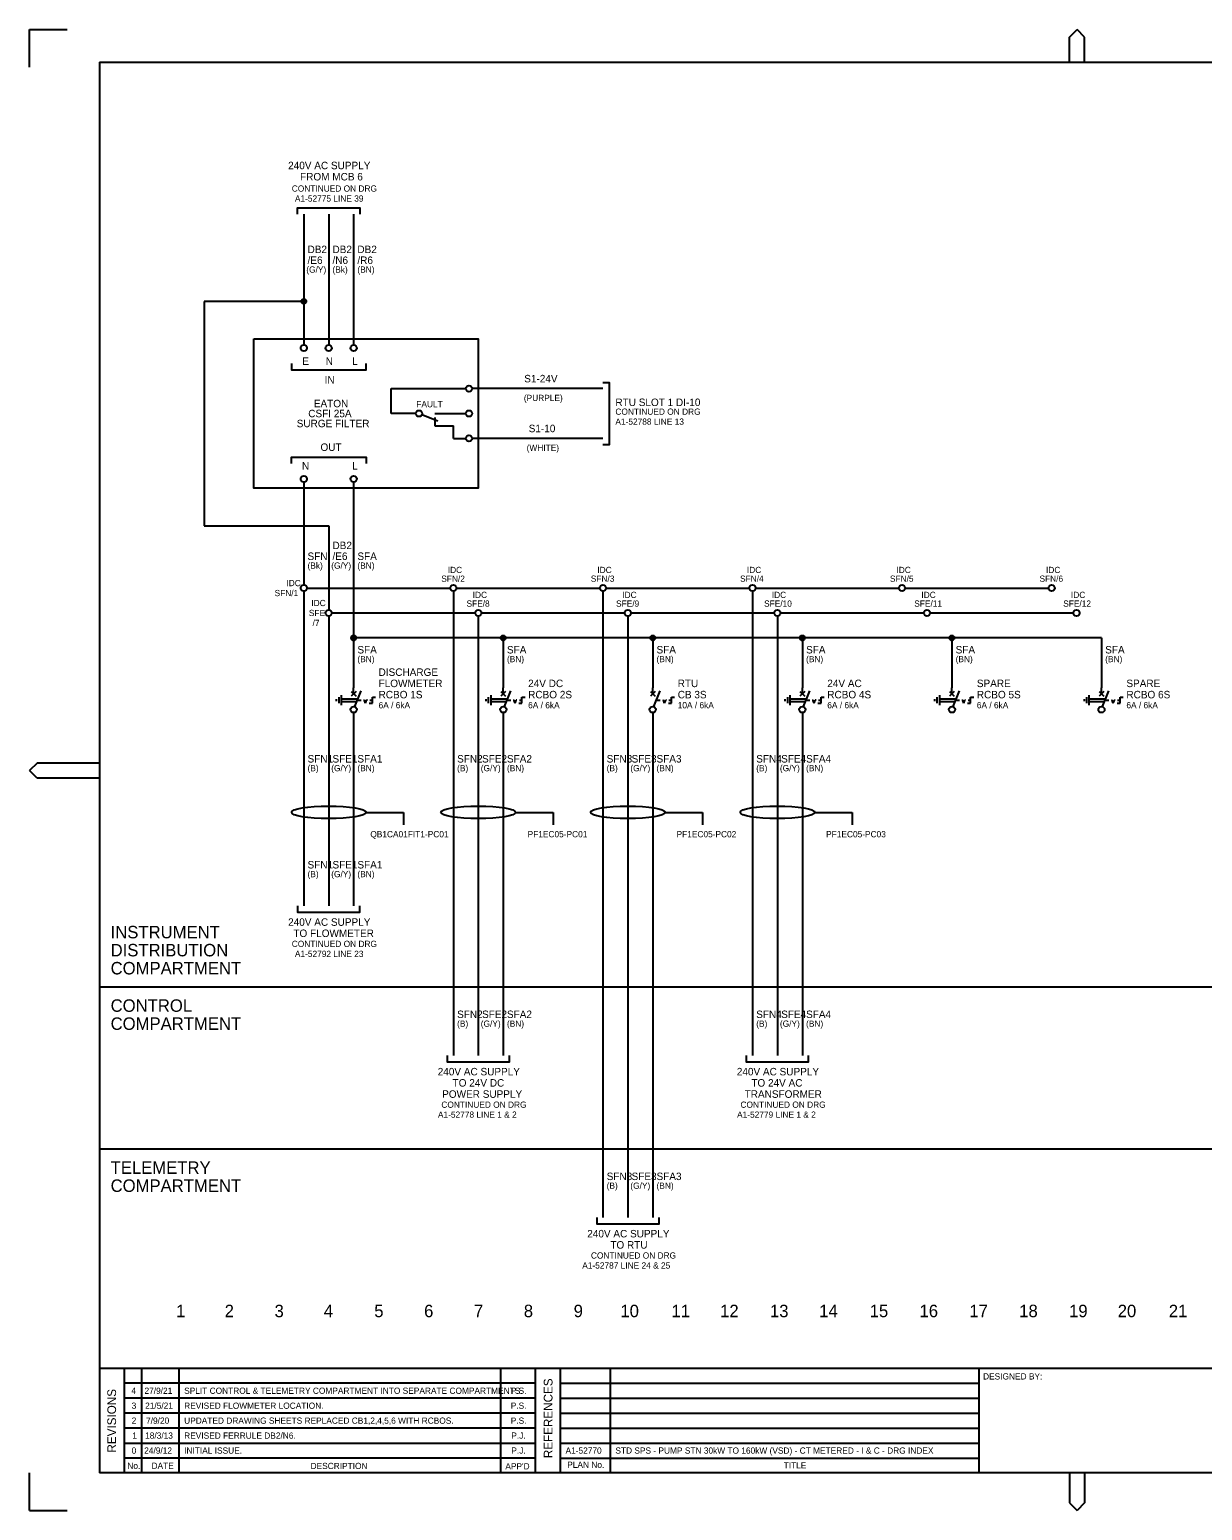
# Model space of a CAD drawing. Extents: x 0 to 841, y 0 to 594.
# Drawn here: x 0 to 470, y 0 to 594 of the extents above; entities that cross this region are included whole.
import ezdxf

# ---------------------------------------------------------------- set-up
doc = ezdxf.new("R2010")
doc.units = 0
for name, color, linetype in [('A1BORDER', 7, 'Continuous'), ('Level 1', 7, 'Continuous'), ('Level 10', 7, 'Continuous')]:
    doc.layers.add(name, color=color, linetype=linetype)

msp = doc.modelspace()

# ---------------------------------------------------------------- linework, layer by layer
at = {"layer": 'A1BORDER'}
for p, q in [((0, 594), (15, 594)), ((0, 579), (0, 594)), ((417.19, 591), (420.19, 594)), ((423.19, 591), (420.19, 594)), ((417.19, 581), (417.19, 591)), ((423.19, 581), (423.19, 591)), ((28, 581), (829, 581)), ((28, 581), (28, 15)), ((3, 299.76), (0, 296.76)), ((28, 299.76), (3, 299.76)), ((3, 293.76), (0, 296.76)), ((28, 293.76), (3, 293.76)), ((28, 57), (829, 57)), ((38, 15), (38, 57)), ((45, 15), (45, 57)), ((60, 15), (60, 57)), ((189, 15), (189, 57)), ((203, 15), (203, 57)), ((213, 15), (213, 57)), ((233, 15), (233, 57)), ((381, 15), (381, 57)), ((203, 51), (38, 51)), ((213, 51), (381, 51)), ((203, 45), (38, 45)), ((213, 45), (381, 45)), ((203, 39), (38, 39)), ((213, 39), (381, 39)), ((203, 33), (38, 33)), ((213, 33), (381, 33)), ((38, 27), (203, 27)), ((213, 27), (381, 27)), ((203, 21), (38, 21)), ((213, 21), (381, 21)), ((0, 0), (0, 15)), ((829, 15), (28, 15)), ((417.19, 15), (417.19, 3)), ((423.19, 15), (423.19, 3)), ((0, 0), (15, 0)), ((417.19, 3), (420.19, 0)), ((423.19, 3), (420.19, 0))]:
    msp.add_line(p, q, dxfattribs=at)
at = {"layer": 'Level 1'}
for p, q in [((110, 520), (110, 467.5)), ((120, 520), (120, 467.5)), ((130, 520), (130, 467.5)), ((110, 485), (70, 485)), ((70, 485), (70, 395)), ((110, 467.5), (110, 467.5)), ((110, 465), (110, 465)), ((120, 467.5), (120, 467.5)), ((120, 465), (120, 465)), ((130, 467.5), (130, 467.5)), ((130, 465), (130, 465)), ((145, 440), (145, 450)), ((145, 450), (175, 450)), ((176.25, 451.25), (176.25, 451.25)), ((176.25, 448.75), (176.25, 448.75)), ((230, 450), (177.5, 450)), ((155, 440), (145, 440)), ((165, 440), (175, 440)), ((176.25, 441.25), (176.25, 441.25)), ((165, 435), (170, 435)), ((170, 430), (170, 435)), ((176.25, 438.75), (176.25, 438.75)), ((170, 430), (175, 430)), ((176.25, 431.25), (176.25, 431.25)), ((176.25, 428.75), (176.25, 428.75)), ((230, 430), (177.5, 430)), ((110, 415), (110, 415)), ((110, 412.5), (110, 412.5)), ((110, 412.5), (110, 371.25)), ((130, 415), (130, 415)), ((130, 412.5), (130, 412.5)), ((130, 412.5), (130, 330)), ((70, 395), (120, 395)), ((120, 395), (120, 361.25)), ((110, 371.25), (110, 371.25)), ((110, 368.75), (110, 368.75)), ((110, 368.75), (110, 242.5)), ((111.25, 370), (168.75, 370)), ((170, 371.25), (170, 371.25)), ((170, 368.75), (170, 368.75)), ((170, 368.75), (170, 182.5)), ((171.25, 370), (228.75, 370)), ((230, 371.25), (230, 371.25)), ((230, 368.75), (230, 368.75)), ((230, 368.75), (230, 117.5)), ((231.25, 370), (288.75, 370)), ((290, 371.25), (290, 371.25)), ((290, 368.75), (290, 182.5)), ((290, 368.75), (290, 368.75)), ((291.25, 370), (348.75, 370)), ((350, 371.25), (350, 371.25)), ((350, 368.75), (350, 368.75)), ((351.25, 370), (408.75, 370)), ((410, 371.25), (410, 371.25)), ((410, 368.75), (410, 368.75)), ((120, 361.25), (120, 361.25)), ((120, 358.75), (120, 358.75)), ((120, 358.75), (120, 242.5)), ((121.25, 360), (178.75, 360)), ((180, 361.25), (180, 361.25)), ((180, 358.75), (180, 358.75)), ((180, 358.75), (180, 182.5)), ((181.25, 360), (238.75, 360)), ((240, 361.25), (240, 361.25)), ((240, 358.75), (240, 358.75)), ((240, 358.75), (240, 117.5)), ((241.25, 360), (298.75, 360)), ((300, 361.25), (300, 361.25)), ((300, 358.75), (300, 182.5)), ((300, 358.75), (300, 358.75)), ((301.25, 360), (358.75, 360)), ((360, 361.25), (360, 361.25)), ((360, 358.75), (360, 358.75)), ((361.25, 360), (418.75, 360)), ((420, 361.25), (420, 361.25)), ((420, 358.75), (420, 358.75)), ((430, 350), (130, 350)), ((190, 350), (190, 330)), ((250, 350), (250, 330)), ((310, 350), (310, 330)), ((370, 350), (370, 330)), ((430, 350), (430, 330)), ((129.06, 328.44), (130.94, 326.56)), ((130.94, 328.44), (129.06, 326.56)), ((130, 327.5), (130, 330)), ((130.46, 322.41), (133, 328.75)), ((189.06, 328.44), (190.94, 326.56)), ((190.94, 328.44), (189.06, 326.56)), ((190, 327.5), (190, 330)), ((190.46, 322.41), (193, 328.75)), ((249.06, 328.44), (250.94, 326.56)), ((250.94, 328.44), (249.06, 326.56)), ((250, 327.5), (250, 330)), ((250.46, 322.41), (253, 328.75)), ((309.06, 328.44), (310.94, 326.56)), ((310.94, 328.44), (309.06, 326.56)), ((310, 327.5), (310, 330)), ((310.46, 322.41), (313, 328.75)), ((369.06, 328.44), (370.94, 326.56)), ((370.94, 328.44), (369.06, 326.56)), ((370, 327.5), (370, 330)), ((370.46, 322.41), (373, 328.75)), ((429.06, 328.44), (430.94, 326.56)), ((430.94, 328.44), (429.06, 326.56)), ((430, 327.5), (430, 330)), ((430.46, 322.41), (433, 328.75)), ((125, 325.5), (131.7, 325.5)), ((125, 324.5), (131.3, 324.5)), ((185, 325.5), (191.7, 325.5)), ((185, 324.5), (191.3, 324.5)), ((305, 325.5), (311.7, 325.5)), ((305, 324.5), (311.3, 324.5)), ((365, 325.5), (371.7, 325.5)), ((365, 324.5), (371.3, 324.5)), ((425, 325.5), (431.7, 325.5)), ((425, 324.5), (431.3, 324.5)), ((130, 320), (130, 242.5)), ((190, 320), (190, 182.5)), ((250, 320), (250, 117.5)), ((310, 320), (310, 182.5)), ((135, 280), (150, 280)), ((150, 280), (150, 275)), ((195, 280), (210, 280)), ((210, 280), (210, 275)), ((255, 280), (270, 280)), ((270, 280), (270, 275)), ((315, 280), (330, 280)), ((330, 280), (330, 275)), ((28, 210), (829, 210)), ((28, 145), (829, 145))]:
    msp.add_line(p, q, dxfattribs=at)
for points in [[(107.5, 520), (107.5, 522.5), (132.5, 522.5), (132.5, 520)], [(105, 460), (105, 457.5), (135, 457.5), (135, 460)], [(230, 452.5), (232.5, 452.5), (232.5, 427.5), (230, 427.5)], [(105, 420), (105, 422.5), (135, 422.5), (135, 420)], [(107.5, 242.5), (107.5, 240), (132.5, 240), (132.5, 242.5)], [(167.5, 182.5), (167.5, 180), (192.5, 180), (192.5, 182.5)], [(287.5, 182.5), (287.5, 180), (312.5, 180), (312.5, 182.5)], [(227.5, 117.5), (227.5, 115), (252.5, 115), (252.5, 117.5)]]:
    msp.add_lwpolyline(points, dxfattribs=at)
msp.add_lwpolyline([(90, 470), (180, 470), (180, 410), (90, 410)], close=True, dxfattribs=at)
for centre in [(130, 321.25), (190, 321.25), (250, 321.25), (310, 321.25), (370, 321.25), (430, 321.25)]:
    msp.add_circle(centre, 1.25, dxfattribs=at)
for centre in [(120, 280), (180, 280), (240, 280), (300, 280)]:
    msp.add_ellipse(centre, major_axis=(-15, 0), ratio=0.166667, dxfattribs=at)
at = {"layer": 'Level 10'}
for p, q in [((109, 485), (110.99, 485)), ((109.05, 485.3), (110.95, 485.3)), ((109.05, 484.7), (110.95, 484.7)), ((109.2, 485.6), (110.8, 485.6)), ((109.2, 484.4), (110.8, 484.4)), ((109.56, 485.9), (110.44, 485.9)), ((109.56, 484.1), (110.44, 484.1)), ((110, 486), (110, 486)), ((162.5, 440), (165, 440)), ((157.41, 439.54), (163.75, 437)), ((162.5, 438.37), (162.5, 435)), ((162.5, 435), (165, 435)), ((129.2, 350.6), (130.8, 350.6)), ((129.56, 350.9), (130.44, 350.9)), ((130, 351), (130, 351)), ((189.2, 350.6), (190.8, 350.6)), ((189.56, 350.9), (190.44, 350.9)), ((190, 351), (190, 351)), ((249.2, 350.6), (250.8, 350.6)), ((249.56, 350.9), (250.44, 350.9)), ((250, 351), (250, 351)), ((309.2, 350.6), (310.8, 350.6)), ((309.56, 350.9), (310.44, 350.9)), ((310, 351), (310, 351)), ((369.2, 350.6), (370.8, 350.6)), ((369.56, 350.9), (370.44, 350.9)), ((370, 351), (370, 351)), ((129, 350), (130.99, 350)), ((129.05, 350.3), (130.95, 350.3)), ((129.05, 349.7), (130.95, 349.7)), ((129.2, 349.4), (130.8, 349.4)), ((129.56, 349.1), (130.44, 349.1)), ((189, 350), (190.99, 350)), ((189.05, 350.3), (190.95, 350.3)), ((189.05, 349.7), (190.95, 349.7)), ((189.2, 349.4), (190.8, 349.4)), ((189.56, 349.1), (190.44, 349.1)), ((249, 350), (250.99, 350)), ((249.05, 350.3), (250.95, 350.3)), ((249.05, 349.7), (250.95, 349.7)), ((249.2, 349.4), (250.8, 349.4)), ((249.56, 349.1), (250.44, 349.1)), ((309, 350), (310.99, 350)), ((309.05, 350.3), (310.95, 350.3)), ((309.05, 349.7), (310.95, 349.7)), ((309.2, 349.4), (310.8, 349.4)), ((309.56, 349.1), (310.44, 349.1)), ((369, 350), (370.99, 350)), ((369.05, 350.3), (370.95, 350.3)), ((369.05, 349.7), (370.95, 349.7)), ((369.2, 349.4), (370.8, 349.4)), ((369.56, 349.1), (370.44, 349.1)), ((125, 327), (125, 323)), ((185, 327), (185, 323)), ((305, 327), (305, 323)), ((365, 327), (365, 323)), ((425, 327), (425, 323)), ((123, 325.4), (123, 324.6)), ((124, 326.2), (124, 323.8)), ((131.5, 325), (133, 325)), ((134, 325), (134.33, 325)), ((134.75, 323.75), (134.33, 325)), ((134.75, 323.75), (135.17, 325)), ((135.5, 325), (135.17, 325)), ((136.25, 323.75), (137.5, 323.75)), ((136.5, 325), (137.5, 325)), ((137.5, 323.75), (137.5, 326.25)), ((137.5, 326.25), (138.75, 326.25)), ((183, 325.4), (183, 324.6)), ((184, 326.2), (184, 323.8)), ((191.5, 325), (193, 325)), ((194, 325), (194.33, 325)), ((194.75, 323.75), (194.33, 325)), ((194.75, 323.75), (195.17, 325)), ((195.5, 325), (195.17, 325)), ((196.25, 323.75), (197.5, 323.75)), ((196.5, 325), (197.5, 325)), ((197.5, 323.75), (197.5, 326.25)), ((197.5, 326.25), (198.75, 326.25)), ((251.5, 325), (253, 325)), ((254, 325), (254.33, 325)), ((254.75, 323.75), (254.33, 325)), ((254.75, 323.75), (255.17, 325)), ((255.5, 325), (255.17, 325)), ((256.25, 323.75), (257.5, 323.75)), ((256.5, 325), (257.5, 325)), ((257.5, 323.75), (257.5, 326.25)), ((257.5, 326.25), (258.75, 326.25)), ((303, 325.4), (303, 324.6)), ((304, 326.2), (304, 323.8)), ((311.5, 325), (313, 325)), ((314, 325), (314.33, 325)), ((314.75, 323.75), (314.33, 325)), ((314.75, 323.75), (315.17, 325)), ((315.5, 325), (315.17, 325)), ((316.25, 323.75), (317.5, 323.75)), ((316.5, 325), (317.5, 325)), ((317.5, 323.75), (317.5, 326.25)), ((317.5, 326.25), (318.75, 326.25)), ((363, 325.4), (363, 324.6)), ((364, 326.2), (364, 323.8)), ((371.5, 325), (373, 325)), ((374, 325), (374.33, 325)), ((374.75, 323.75), (374.33, 325)), ((374.75, 323.75), (375.17, 325)), ((375.5, 325), (375.17, 325)), ((376.25, 323.75), (377.5, 323.75)), ((376.5, 325), (377.5, 325)), ((377.5, 323.75), (377.5, 326.25)), ((377.5, 326.25), (378.75, 326.25)), ((423, 325.4), (423, 324.6)), ((424, 326.2), (424, 323.8)), ((431.5, 325), (433, 325)), ((434, 325), (434.33, 325)), ((434.75, 323.75), (434.33, 325)), ((434.75, 323.75), (435.17, 325)), ((435.5, 325), (435.17, 325)), ((436.25, 323.75), (437.5, 323.75)), ((436.5, 325), (437.5, 325)), ((437.5, 323.75), (437.5, 326.25)), ((437.5, 326.25), (438.75, 326.25))]:
    msp.add_line(p, q, dxfattribs=at)
for centre, radius in [((110, 485), 1), ((110, 466.25), 1.25), ((120, 466.25), 1.25), ((130, 466.25), 1.25), ((176.25, 450), 1.25), ((156.25, 440), 1.25), ((176.25, 440), 1.25), ((176.25, 430), 1.25), ((110, 413.75), 1.25), ((130, 413.75), 1.25), ((110, 370), 1.25), ((170, 370), 1.25), ((230, 370), 1.25), ((290, 370), 1.25), ((350, 370), 1.25), ((410, 370), 1.25), ((120, 360), 1.25), ((180, 360), 1.25), ((240, 360), 1.25), ((300, 360), 1.25), ((360, 360), 1.25), ((420, 360), 1.25), ((130, 350), 1), ((190, 350), 1), ((250, 350), 1), ((310, 350), 1), ((370, 350), 1)]:
    msp.add_circle(centre, radius, dxfattribs=at)

# ---------------------------------------------------------------- texts
at = {"layer": 'A1BORDER'}
for s, p in [('DESIGNED BY:', (382.5, 52.5)), ('No.', (39.21, 16.65)), ('DATE', (48.92, 16.65)), ('DESCRIPTION', (112.71, 16.57)), ("APP'D", (190.85, 16.44)), ('PLAN No.', (215.69, 17.06)), ('TITLE', (302.5, 16.81))]:
    msp.add_text(s, height=2.5, dxfattribs=at).set_placement(p)
for s, p in [('REVISIONS', (34.68, 23.2)), ('REFERENCES', (209.76, 20.96))]:
    msp.add_text(s, height=3.5, rotation=90, dxfattribs=at).set_placement(p)
at = {"layer": 'Level 1'}
for s, height, p in [('240V AC SUPPLY', 3, (103.71, 538)), ('FROM MCB 6', 3, (108.5, 533.5)), ('CONTINUED ON DRG', 2.5, (105.18, 529)), ('A1-52775 LINE 39', 2.5, (106.43, 525)), ('DB2', 3, (111.5, 504.34)), ('DB2', 3, (121.5, 504.34)), ('DB2', 3, (131.5, 504.34)), ('(G/Y)', 2.5, (111, 496.5)), ('/E6', 3, (111.5, 500)), ('/N6', 3, (121.5, 500)), ('(Bk)', 2.5, (121.5, 496.5)), ('/R6', 3, (131.5, 500)), ('(BN)', 2.5, (131.5, 496.5)), ('E', 3, (109.4, 459.5)), ('N', 3, (118.8, 459.5)), ('L', 3, (129.4, 459.5)), ('IN', 3, (118.35, 452)), ('S1-24V', 3, (198.43, 452.5)), ('EATON', 3, (114.02, 442.5)), ('(PURPLE)', 2.5, (198.28, 445)), ('RTU SLOT 1 DI-10', 3, (235, 443)), ('CSFI 25A', 3, (111.78, 438.5)), ('FAULT', 2.5, (155.14, 442.5)), ('CONTINUED ON DRG', 2.5, (235, 439.5)), ('SURGE FILTER', 3, (107.15, 434.5)), ('S1-10', 3, (200.22, 432.5)), ('A1-52788 LINE 13', 2.5, (235, 435.5)), ('OUT', 3, (116.7, 425)), ('(WHITE)', 2.5, (199.4, 425)), ('N', 3, (109.26, 417.5)), ('L', 3, (129.4, 417.5)), ('DB2', 3, (121.5, 385.59)), ('SFN', 3, (111.5, 381.25)), ('(Bk)', 2.5, (111.5, 377.75)), ('(G/Y)', 2.5, (121, 377.75)), ('/E6', 3, (121.5, 381.25)), ('SFA', 3, (131.5, 381.25)), ('(BN)', 2.5, (131.5, 377.75)), ('SFN/2', 2.5, (165.14, 372.5)), ('IDC', 2.5, (167.76, 376)), ('SFN/3', 2.5, (225.14, 372.5)), ('IDC', 2.5, (227.76, 376)), ('SFN/4', 2.5, (285.02, 372.5)), ('IDC', 2.5, (287.76, 376)), ('SFN/5', 2.5, (345.14, 372.5)), ('IDC', 2.5, (347.76, 376)), ('SFN/6', 2.5, (405.14, 372.5)), ('IDC', 2.5, (407.76, 376)), ('SFN/1', 2.5, (98.29, 366.74)), ('IDC', 2.5, (103.02, 370.74)), ('IDC', 2.5, (177.76, 366)), ('IDC', 2.5, (237.76, 366)), ('IDC', 2.5, (297.76, 366)), ('IDC', 2.5, (357.76, 366)), ('IDC', 2.5, (417.76, 366)), ('IDC', 2.5, (113.02, 362.74)), ('SFE/8', 2.5, (175.27, 362.5)), ('SFE/9', 2.5, (235.27, 362.5)), ('SFE/10', 2.5, (294.65, 362.5)), ('SFE/11', 2.5, (354.89, 362.5)), ('SFE/12', 2.5, (414.65, 362.5)), ('SFE', 2.5, (112.02, 358.74)), ('/7', 2.5, (113.52, 354.74)), ('SFA', 3, (131.5, 343.75)), ('SFA', 3, (191.5, 343.75)), ('SFA', 3, (251.5, 343.75)), ('SFA', 3, (311.5, 343.75)), ('SFA', 3, (371.5, 343.75)), ('SFA', 3, (431.5, 343.75)), ('(BN)', 2.5, (131.5, 340.25)), ('(BN)', 2.5, (191.5, 340.25)), ('(BN)', 2.5, (251.5, 340.25)), ('(BN)', 2.5, (311.5, 340.25)), ('(BN)', 2.5, (371.5, 340.25)), ('(BN)', 2.5, (431.5, 340.25)), ('DISCHARGE', 3, (140, 334.75)), ('FLOWMETER', 3, (140, 330.25)), ('24V DC', 3, (200, 330.25)), ('RTU', 3, (260, 330.25)), ('24V AC', 3, (320, 330.25)), ('SPARE', 3, (380, 330.25)), ('SPARE', 3, (440, 330.25)), ('RCBO 1S', 3, (140, 325.75)), ('RCBO 2S', 3, (200, 325.75)), ('CB 3S', 3, (260, 325.75)), ('RCBO 4S', 3, (320, 325.75)), ('RCBO 5S', 3, (380, 325.75)), ('RCBO 6S', 3, (440, 325.75)), ('6A / 6kA', 2.5, (140, 321.75)), ('6A / 6kA', 2.5, (200, 321.75)), ('10A / 6kA', 2.5, (260, 321.75)), ('6A / 6kA', 2.5, (320, 321.75)), ('6A / 6kA', 2.5, (380, 321.75)), ('6A / 6kA', 2.5, (440, 321.75)), ('SFN1', 3, (111.5, 300)), ('SFE1', 3, (121.5, 300)), ('SFA1', 3, (131.5, 300)), ('SFN2', 3, (171.5, 300)), ('SFE2', 3, (181.5, 300)), ('SFA2', 3, (191.5, 300)), ('SFN3', 3, (231.5, 300)), ('SFE3', 3, (241.5, 300)), ('SFA3', 3, (251.5, 300)), ('SFN4', 3, (291.5, 300)), ('SFE4', 3, (301.5, 300)), ('SFA4', 3, (311.5, 300)), ('(B)', 2.5, (111.5, 296.5)), ('(G/Y)', 2.5, (121, 296.5)), ('(BN)', 2.5, (131.5, 296.5)), ('(B)', 2.5, (171.5, 296.5)), ('(G/Y)', 2.5, (181, 296.5)), ('(BN)', 2.5, (191.5, 296.5)), ('(B)', 2.5, (231.5, 296.5)), ('(G/Y)', 2.5, (241, 296.5)), ('(BN)', 2.5, (251.5, 296.5)), ('(B)', 2.5, (291.5, 296.5)), ('(G/Y)', 2.5, (301, 296.5)), ('(BN)', 2.5, (311.5, 296.5)), ('QB1CA01FIT1-PC01', 2.5, (136.68, 270)), ('PF1EC05-PC01', 2.5, (199.79, 270)), ('PF1EC05-PC02', 2.5, (259.54, 270)), ('PF1EC05-PC03', 2.5, (319.54, 270)), ('SFN1', 3, (111.5, 257.5)), ('(B)', 2.5, (111.5, 254)), ('(G/Y)', 2.5, (121, 254)), ('SFE1', 3, (121.5, 257.5)), ('SFA1', 3, (131.5, 257.5)), ('(BN)', 2.5, (131.5, 254)), ('INSTRUMENT', 5, (32.5, 229.47)), ('240V AC SUPPLY', 3, (103.71, 234.5)), ('TO FLOWMETER', 3, (105.81, 230)), ('DISTRIBUTION', 5, (32.5, 222.24)), ('CONTINUED ON DRG', 2.5, (105.18, 226)), ('COMPARTMENT', 5, (32.5, 215)), ('A1-52792 LINE 23', 2.5, (106.43, 222)), ('CONTROL', 5, (32.5, 200)), ('COMPARTMENT', 5, (32.5, 192.76)), ('SFN2', 3, (171.5, 197.5)), ('(B)', 2.5, (171.5, 194)), ('(G/Y)', 2.5, (181, 194)), ('SFE2', 3, (181.5, 197.5)), ('SFA2', 3, (191.5, 197.5)), ('(BN)', 2.5, (191.5, 194)), ('SFN4', 3, (291.5, 197.5)), ('(B)', 2.5, (291.5, 194)), ('(G/Y)', 2.5, (301, 194)), ('SFE4', 3, (301.5, 197.5)), ('SFA4', 3, (311.5, 197.5)), ('(BN)', 2.5, (311.5, 194)), ('240V AC SUPPLY', 3, (163.71, 174.5)), ('TO 24V DC', 3, (169.69, 170)), ('240V AC SUPPLY', 3, (283.71, 174.5)), ('TO 24V AC', 3, (289.54, 170)), ('POWER SUPPLY', 3, (165.51, 165.5)), ('TRANSFORMER', 3, (286.85, 165.5)), ('CONTINUED ON DRG', 2.5, (165.18, 161.5)), ('CONTINUED ON DRG', 2.5, (285.18, 161.5)), ('A1-52778 LINE 1 & 2', 2.5, (163.81, 157.5)), ('A1-52779 LINE 1 & 2', 2.5, (283.81, 157.5)), ('TELEMETRY', 5, (32.5, 135)), ('COMPARTMENT', 5, (32.5, 127.76)), ('SFN3', 3, (231.5, 132.5)), ('(B)', 2.5, (231.5, 129)), ('(G/Y)', 2.5, (241, 129)), ('SFE3', 3, (241.5, 132.5)), ('SFA3', 3, (251.5, 132.5)), ('(BN)', 2.5, (251.5, 129)), ('240V AC SUPPLY', 3, (223.71, 109.5)), ('TO RTU', 3, (232.98, 105)), ('CONTINUED ON DRG', 2.5, (225.18, 101)), ('A1-52787 LINE 24 & 25', 2.5, (221.7, 97)), ('1', 5, (58.76, 77.5)), ('2', 5, (78.26, 77.5)), ('3', 5, (98.26, 77.5)), ('4', 5, (118.01, 77.5)), ('5', 5, (138.26, 77.5)), ('6', 5, (158.26, 77.5)), ('7', 5, (178.26, 77.5)), ('8', 5, (198.26, 77.5)), ('9', 5, (218.26, 77.5)), ('10', 5, (237.01, 77.5)), ('11', 5, (257.51, 77.5)), ('12', 5, (277.01, 77.5)), ('13', 5, (297.01, 77.5)), ('14', 5, (316.76, 77.5)), ('15', 5, (337.01, 77.5)), ('16', 5, (357.01, 77.5)), ('17', 5, (377.01, 77.5)), ('18', 5, (397.01, 77.5)), ('19', 5, (417.01, 77.5)), ('20', 5, (436.52, 77.5)), ('21', 5, (457.01, 77.5)), ('4', 2.5, (40.82, 46.75)), ('27/9/21', 2.5, (46.09, 46.75)), ('SPLIT CONTROL & TELEMETRY COMPARTMENT INTO SEPARATE COMPARTMENTS.', 2.5, (62, 46.75)), ('P.S.', 2.5, (193.02, 46.75)), ('3', 2.5, (40.94, 40.75)), ('21/5/21', 2.5, (46.34, 40.75)), ('REVISED FLOWMETER LOCATION.', 2.5, (62, 40.75)), ('P.S.', 2.5, (193.02, 40.75)), ('2', 2.5, (40.94, 34.75)), ('7/9/20', 2.5, (46.72, 34.75)), ('UPDATED DRAWING SHEETS REPLACED CB1,2,4,5,6 WITH RCBOS.', 2.5, (62, 34.75)), ('P.S.', 2.5, (193.02, 34.75)), ('1', 2.5, (41.19, 28.75)), ('18/3/13', 2.5, (46.34, 28.75)), ('REVISED FERRULE DB2/N6.', 2.5, (62, 28.75)), ('P.J.', 2.5, (193.26, 28.75)), ('0', 2.5, (40.94, 22.75)), ('24/9/12', 2.5, (45.97, 22.75)), ('INITIAL ISSUE.', 2.5, (62, 22.75)), ('P.J.', 2.5, (193.26, 22.75)), ('A1-52770', 2.5, (215, 22.75)), ('STD SPS - PUMP STN 30kW TO 160kW (VSD) - CT METERED - I & C - DRG INDEX', 2.5, (235, 22.75))]:
    msp.add_text(s, height=height, dxfattribs=at).set_placement(p)

doc.saveas('drawing.dxf')
